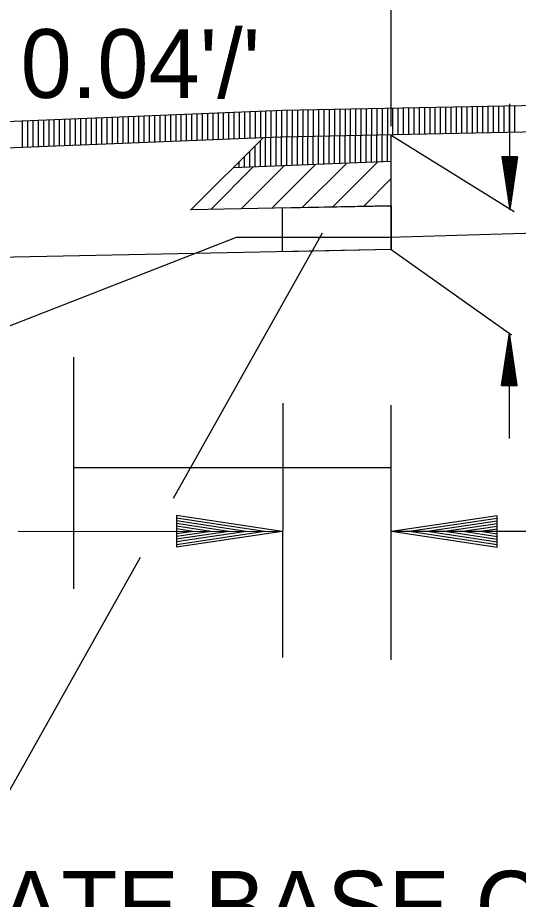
# Model space of a CAD drawing. Extents: x 1373719 to 1374161, y 379835 to 380167.
# Drawn here: x 1373951.52 to 1373956.25, y 380106.35 to 380114.69 of the extents above; entities that cross this region are included whole.
import ezdxf

# ---------------------------------------------------------------- set-up
doc = ezdxf.new("R2010")
doc.units = 0
for name, color, linetype in [('ACHM Surface', 7, 'Continuous'), ('Agg Base Course Text', 7, 'Continuous'), ('Binder', 7, 'Continuous'), ('GREEN_TXT', 7, 'Continuous'), ('Pavement Layers', 7, 'Continuous'), ('SIGNATURE', 7, 'Continuous'), ('T_Drafting', 7, 'Continuous'), ('Text 1', 7, 'Continuous')]:
    doc.layers.add(name, color=color, linetype=linetype)

msp = doc.modelspace()

# ---------------------------------------------------------------- linework, layer by layer
for p, q in [((1373965.0177, 380114.0302), (1373954.0199, 380113.8103)), ((1373954.0199, 380113.8103), (1373950.0231, 380113.6504)), ((1373965.0177, 380113.7802), (1373954.0199, 380113.5603)), ((1373954.0801, 380113.5615), (1373950.0197, 380113.3999)), ((1373955.0445, 380113.3309), (1373953.5528, 380113.2712)), ((1373955.0445, 380112.9109), (1373953.1547, 380112.8731)), ((1373955.0445, 380112.4971), (1373944.5723, 380112.2877))]:
    msp.add_line(p, q)
msp.add_lwpolyline([(1373953.8332, 380113.5516), (1373953.1497, 380112.8681)])
at = {"layer": 'ACHM Surface'}
for p, q in [((1373954.7131, 380113.5741), (1373954.7131, 380113.8241)), ((1373954.7631, 380113.5751), (1373954.7631, 380113.8251)), ((1373954.8131, 380113.5761), (1373954.8131, 380113.8261)), ((1373954.8631, 380113.5771), (1373954.8631, 380113.8271)), ((1373954.9131, 380113.5781), (1373954.9131, 380113.8281)), ((1373954.9631, 380113.5791), (1373954.9631, 380113.8291)), ((1373955.0131, 380113.5801), (1373955.0131, 380113.8301)), ((1373955.0631, 380113.5811), (1373955.0631, 380113.8311)), ((1373955.1131, 380113.5821), (1373955.1131, 380113.8321)), ((1373955.1631, 380113.5831), (1373955.1631, 380113.8331)), ((1373955.2131, 380113.5841), (1373955.2131, 380113.8341)), ((1373955.2631, 380113.5851), (1373955.2631, 380113.8351)), ((1373955.3131, 380113.5861), (1373955.3131, 380113.8361)), ((1373955.3631, 380113.5871), (1373955.3631, 380113.8371)), ((1373955.4131, 380113.5881), (1373955.4131, 380113.8381)), ((1373955.4631, 380113.5891), (1373955.4631, 380113.8391)), ((1373955.5131, 380113.5901), (1373955.5131, 380113.8401)), ((1373955.5631, 380113.5911), (1373955.5631, 380113.8411)), ((1373955.6131, 380113.5921), (1373955.6131, 380113.8421)), ((1373955.6631, 380113.5931), (1373955.6631, 380113.8431)), ((1373955.7131, 380113.5941), (1373955.7131, 380113.8441)), ((1373955.7631, 380113.5951), (1373955.7631, 380113.8451)), ((1373955.8131, 380113.5961), (1373955.8131, 380113.8461)), ((1373955.8631, 380113.5971), (1373955.8631, 380113.8471)), ((1373955.9131, 380113.5981), (1373955.9131, 380113.8481)), ((1373955.9631, 380113.5991), (1373955.9631, 380113.8491)), ((1373956.0131, 380113.6001), (1373956.0131, 380113.8501)), ((1373956.0631, 380113.6011), (1373956.0631, 380113.8511)), ((1373956.1131, 380113.6021), (1373956.1131, 380113.8521)), ((1373956.1631, 380113.6031), (1373956.1631, 380113.8531)), ((1373956.2131, 380113.6041), (1373956.2131, 380113.8541)), ((1373952.3131, 380113.4912), (1373952.3131, 380113.742)), ((1373952.3631, 380113.4931), (1373952.3631, 380113.744)), ((1373952.4131, 380113.4951), (1373952.4131, 380113.746)), ((1373952.4631, 380113.4971), (1373952.4631, 380113.748)), ((1373952.5131, 380113.4991), (1373952.5131, 380113.75)), ((1373952.5631, 380113.5011), (1373952.5631, 380113.752)), ((1373952.6131, 380113.5031), (1373952.6131, 380113.754)), ((1373952.6631, 380113.5051), (1373952.6631, 380113.756)), ((1373952.7131, 380113.5071), (1373952.7131, 380113.758)), ((1373952.7631, 380113.5091), (1373952.7631, 380113.76)), ((1373952.8131, 380113.511), (1373952.8131, 380113.762)), ((1373952.8631, 380113.513), (1373952.8631, 380113.764)), ((1373952.9131, 380113.515), (1373952.9131, 380113.766)), ((1373952.9631, 380113.517), (1373952.9631, 380113.768)), ((1373953.0131, 380113.519), (1373953.0131, 380113.77)), ((1373953.0631, 380113.521), (1373953.0631, 380113.772)), ((1373953.1131, 380113.523), (1373953.1131, 380113.774)), ((1373953.1631, 380113.525), (1373953.1631, 380113.776)), ((1373953.2131, 380113.527), (1373953.2131, 380113.778)), ((1373953.2631, 380113.529), (1373953.2631, 380113.78)), ((1373953.3131, 380113.5309), (1373953.3131, 380113.782)), ((1373953.3631, 380113.5329), (1373953.3631, 380113.784)), ((1373953.4131, 380113.5349), (1373953.4131, 380113.786)), ((1373953.4631, 380113.5369), (1373953.4631, 380113.788)), ((1373953.5131, 380113.5389), (1373953.5131, 380113.79)), ((1373953.5631, 380113.5409), (1373953.5631, 380113.792)), ((1373953.6131, 380113.5429), (1373953.6131, 380113.794)), ((1373953.6631, 380113.5449), (1373953.6631, 380113.796)), ((1373953.7131, 380113.5469), (1373953.7131, 380113.798)), ((1373953.7631, 380113.5489), (1373953.7631, 380113.8)), ((1373953.8131, 380113.5508), (1373953.8131, 380113.802)), ((1373953.8631, 380113.5528), (1373953.8631, 380113.804)), ((1373953.9131, 380113.5548), (1373953.9131, 380113.806)), ((1373953.9631, 380113.5568), (1373953.9631, 380113.808)), ((1373954.0131, 380113.5588), (1373954.0131, 380113.81)), ((1373954.0631, 380113.5611), (1373954.0631, 380113.8111)), ((1373954.1131, 380113.5621), (1373954.1131, 380113.8121)), ((1373954.1631, 380113.5631), (1373954.1631, 380113.8131)), ((1373954.2131, 380113.5641), (1373954.2131, 380113.8141)), ((1373954.2631, 380113.5651), (1373954.2631, 380113.8151)), ((1373954.3131, 380113.5661), (1373954.3131, 380113.8161)), ((1373954.3631, 380113.5671), (1373954.3631, 380113.8171)), ((1373954.4131, 380113.5681), (1373954.4131, 380113.8181)), ((1373954.4631, 380113.5691), (1373954.4631, 380113.8191)), ((1373954.5131, 380113.5701), (1373954.5131, 380113.8201)), ((1373954.5631, 380113.5711), (1373954.5631, 380113.8211)), ((1373954.6131, 380113.5721), (1373954.6131, 380113.8221)), ((1373954.6631, 380113.5731), (1373954.6631, 380113.8231)), ((1373951.5631, 380113.4613), (1373951.5631, 380113.712)), ((1373951.6131, 380113.4633), (1373951.6131, 380113.714)), ((1373951.6631, 380113.4653), (1373951.6631, 380113.716)), ((1373951.7131, 380113.4673), (1373951.7131, 380113.718)), ((1373951.7631, 380113.4693), (1373951.7631, 380113.72)), ((1373951.8131, 380113.4713), (1373951.8131, 380113.722)), ((1373951.8631, 380113.4732), (1373951.8631, 380113.724)), ((1373951.9131, 380113.4752), (1373951.9131, 380113.726)), ((1373951.9631, 380113.4772), (1373951.9631, 380113.728)), ((1373952.0131, 380113.4792), (1373952.0131, 380113.73)), ((1373952.0631, 380113.4812), (1373952.0631, 380113.732)), ((1373952.1131, 380113.4832), (1373952.1131, 380113.734)), ((1373952.1631, 380113.4852), (1373952.1631, 380113.736)), ((1373952.2131, 380113.4872), (1373952.2131, 380113.738)), ((1373952.2631, 380113.4892), (1373952.2631, 380113.74)), ((1373954.7099, 380113.3175), (1373954.7099, 380113.5741)), ((1373954.7599, 380113.3195), (1373954.7599, 380113.5751)), ((1373954.8099, 380113.3215), (1373954.8099, 380113.5761)), ((1373954.8599, 380113.3235), (1373954.8599, 380113.5771)), ((1373954.9099, 380113.3255), (1373954.9099, 380113.5781)), ((1373954.9599, 380113.3275), (1373954.9599, 380113.5791)), ((1373955.0099, 380113.3295), (1373955.0099, 380113.5801)), ((1373953.8099, 380113.2815), (1373953.8099, 380113.5283)), ((1373953.8599, 380113.2835), (1373953.8599, 380113.5527)), ((1373953.9099, 380113.2855), (1373953.9099, 380113.5547)), ((1373953.9599, 380113.2875), (1373953.9599, 380113.5567)), ((1373954.0099, 380113.2895), (1373954.0099, 380113.5587)), ((1373954.0599, 380113.2915), (1373954.0599, 380113.5607)), ((1373954.1099, 380113.2935), (1373954.1099, 380113.5621)), ((1373954.1599, 380113.2955), (1373954.1599, 380113.5631)), ((1373954.2099, 380113.2975), (1373954.2099, 380113.5641)), ((1373954.2599, 380113.2995), (1373954.2599, 380113.5651)), ((1373954.3099, 380113.3015), (1373954.3099, 380113.5661)), ((1373954.3599, 380113.3035), (1373954.3599, 380113.5671)), ((1373954.4099, 380113.3055), (1373954.4099, 380113.5681)), ((1373954.4599, 380113.3075), (1373954.4599, 380113.5691)), ((1373954.5099, 380113.3095), (1373954.5099, 380113.5701)), ((1373954.5599, 380113.3115), (1373954.5599, 380113.5711)), ((1373954.6099, 380113.3135), (1373954.6099, 380113.5721)), ((1373954.6599, 380113.3155), (1373954.6599, 380113.5731)), ((1373953.7099, 380113.2775), (1373953.7099, 380113.4283)), ((1373953.7599, 380113.2795), (1373953.7599, 380113.4783)), ((1373953.6099, 380113.2735), (1373953.6099, 380113.3283)), ((1373953.6599, 380113.2755), (1373953.6599, 380113.3783)), ((1373953.5599, 380113.2715), (1373953.5599, 380113.2783))]:
    msp.add_line(p, q, dxfattribs=at)
at = {"layer": 'Agg Base Course Text'}
for points in [[(1373952.9891, 380110.1476), (1373954.3971, 380112.6552)], [(1373951.297, 380107.1342), (1373952.6759, 380109.5899)]]:
    msp.add_lwpolyline(points, dxfattribs=at)
at = {"layer": 'Binder'}
for p, q in [((1373954.4952, 380112.8999), (1373954.9213, 380113.326)), ((1373953.3407, 380112.8768), (1373953.7428, 380113.2788)), ((1373953.6294, 380112.8826), (1373954.0374, 380113.2906)), ((1373953.918, 380112.8884), (1373954.332, 380113.3024)), ((1373954.2066, 380112.8941), (1373954.6266, 380113.3142)), ((1373954.7838, 380112.9057), (1373955.0464, 380113.1682))]:
    msp.add_line(p, q, dxfattribs=at)
at = {"layer": 'GREEN_TXT'}
for p, q in [((1373955.0445, 380114.0142), (1373955.0445, 380117.3298)), ((1373956.1659, 380112.8736), (1373956.1659, 380113.8736)), ((1373955.0475, 380113.5797), (1373956.2077, 380112.8562)), ((1373956.0909, 380113.3736), (1373956.1659, 380112.8736)), ((1373956.2409, 380113.3736), (1373956.0909, 380113.3736)), ((1373956.1034, 380113.3736), (1373956.1659, 380112.9571)), ((1373956.1161, 380113.3736), (1373956.1659, 380113.0431)), ((1373956.1286, 380113.3736), (1373956.1659, 380113.1263)), ((1373956.1414, 380113.3736), (1373956.1659, 380113.2111)), ((1373956.1541, 380113.3736), (1373956.1659, 380113.2946)), ((1373956.2409, 380113.3736), (1373956.1659, 380112.8736)), ((1373956.1901, 380113.3736), (1373956.1659, 380113.2111)), ((1373956.2156, 380113.3736), (1373956.1659, 380113.0431)), ((1373956.2284, 380113.3736), (1373956.1659, 380112.9571)), ((1373956.2031, 380113.3736), (1373956.1659, 380113.1263)), ((1373956.1776, 380113.3736), (1373956.1659, 380113.2946)), ((1373955.0445, 380112.4971), (1373956.1825, 380111.6913)), ((1373956.0878, 380111.2104), (1373956.1628, 380111.7104)), ((1373956.1628, 380110.7104), (1373956.1628, 380111.7104)), ((1373956.2378, 380111.2104), (1373956.1628, 380111.7104)), ((1373956.1003, 380111.2104), (1373956.1628, 380111.6269)), ((1373956.2253, 380111.2104), (1373956.1628, 380111.6269)), ((1373956.1131, 380111.2104), (1373956.1628, 380111.5409)), ((1373956.2126, 380111.2104), (1373956.1628, 380111.5409)), ((1373956.1256, 380111.2104), (1373956.1628, 380111.4576)), ((1373956.2001, 380111.2104), (1373956.1628, 380111.4576)), ((1373956.1386, 380111.2104), (1373956.1628, 380111.3729)), ((1373956.1873, 380111.2104), (1373956.1628, 380111.3729)), ((1373956.1511, 380111.2104), (1373956.1628, 380111.2894)), ((1373956.1746, 380111.2104), (1373956.1628, 380111.2894)), ((1373956.0878, 380111.2104), (1373956.2378, 380111.2104)), ((1373953.0165, 380109.9851), (1373953.0163, 380109.6851)), ((1373953.0164, 380109.9346), (1373953.6774, 380109.8346)), ((1373953.0164, 380109.9096), (1373953.5109, 380109.8347)), ((1373953.0165, 380109.9851), (1373954.0164, 380109.8343)), ((1373953.0165, 380109.9601), (1373953.8494, 380109.8344)), ((1373956.0481, 380109.9804), (1373955.0481, 380109.8304)), ((1373956.0481, 380109.9554), (1373955.2151, 380109.8304)), ((1373956.0481, 380109.9299), (1373955.3871, 380109.8304)), ((1373956.0481, 380109.6804), (1373956.0481, 380109.9804)), ((1373951.5201, 380109.8343), (1373954.0201, 380109.8323)), ((1373953.0163, 380109.8116), (1373953.1744, 380109.835)), ((1373953.0163, 380109.7861), (1373953.3414, 380109.8348)), ((1373953.0163, 380109.7606), (1373953.5109, 380109.8347)), ((1373953.0163, 380109.7356), (1373953.6774, 380109.8346)), ((1373953.0163, 380109.7101), (1373953.8494, 380109.8344)), ((1373953.0163, 380109.6851), (1373954.0164, 380109.8343)), ((1373953.0164, 380109.8836), (1373953.3414, 380109.8348)), ((1373953.0164, 380109.8586), (1373953.1744, 380109.835)), ((1373975.0445, 380109.8323), (1373955.0445, 380109.8323)), ((1373956.0481, 380109.6804), (1373955.0481, 380109.8304)), ((1373956.0481, 380109.7054), (1373955.2151, 380109.8304)), ((1373956.0481, 380109.7309), (1373955.3871, 380109.8304)), ((1373956.0481, 380109.9049), (1373955.5536, 380109.8304)), ((1373956.0481, 380109.7559), (1373955.5536, 380109.8304)), ((1373956.0481, 380109.8794), (1373955.7231, 380109.8304)), ((1373956.0481, 380109.7819), (1373955.7231, 380109.8304)), ((1373956.0481, 380109.8539), (1373955.8901, 380109.8304)), ((1373956.0481, 380109.8069), (1373955.8901, 380109.8304))]:
    msp.add_line(p, q, dxfattribs=at)
for points in [[(1373954.021, 380111.0459), (1373954.0191, 380108.6398)], [(1373955.0445, 380108.6188), (1373955.0445, 380111.0249)]]:
    msp.add_lwpolyline(points, dxfattribs=at)
at = {"layer": 'Pavement Layers'}
msp.add_line((1373955.0445, 380112.4971), (1373955.0445, 380113.5808), dxfattribs=at)
at = {"layer": 'SIGNATURE'}
msp.add_lwpolyline([(1373954.0199, 380112.8904), (1373955.0445, 380112.9109), (1373955.0445, 380112.4971), (1373954.0199, 380112.4766)], close=True, dxfattribs=at)
at = {"layer": 'T_Drafting'}
msp.add_lwpolyline([(1373907.9866, 380106.5635), (1373924.5328, 380106.4873), (1373943.4495, 380108.6541), (1373953.5849, 380112.614), (1373955.0258, 380112.615), (1373964.8515, 380112.9026), (1373975.0281, 380112.6885), (1373976.6029, 380112.6154), (1373985.6878, 380110.3529), (1373993.9886, 380112.9085), (1374008.917, 380113.95), (1374025.0227, 380113.95)], dxfattribs=at)
at = {"layer": 'Text 1'}
for p, q in [((1373955.0445, 380113.664), (1373955.0445, 380117.2646)), ((1373952.0445, 380111.4812), (1373952.0445, 380109.2897)), ((1373955.0445, 380110.4349), (1373952.0445, 380110.4349))]:
    msp.add_line(p, q, dxfattribs=at)

# ---------------------------------------------------------------- texts
at = {"layer": 'Agg Base Course Text'}
msp.add_text('2\'-0" AGGREGATE BASE CRSE. (CL. 7)', height=0.65, dxfattribs=at).set_placement((1373945.5624, 380105.9732))
at = {"layer": 'GREEN_TXT'}
msp.add_text("0.04'/'", height=0.65, rotation=359.98, dxfattribs=at).set_placement((1373951.5442, 380113.9311))

doc.saveas('drawing.dxf')
